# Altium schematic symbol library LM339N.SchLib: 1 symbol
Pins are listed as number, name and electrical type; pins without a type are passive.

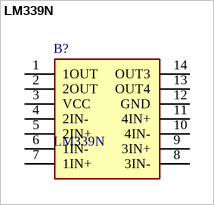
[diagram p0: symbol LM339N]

## LM339N
designator B?
Quad Differential Comparator; Manufacturer_Name: Texas Instruments; Geometry.Height: 5.08mm
footprint DIP794W53P254L1930H508Q14N
pins: 1 1OUT, 2 2OUT, 3 VCC, 4 2IN-, 5 2IN+, 6 1IN-, 7 1IN+, 8 3IN-, 9 3IN+, 10 4IN-, 11 4IN+, 12 GND, 13 OUT4, 14 OUT3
